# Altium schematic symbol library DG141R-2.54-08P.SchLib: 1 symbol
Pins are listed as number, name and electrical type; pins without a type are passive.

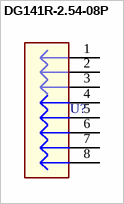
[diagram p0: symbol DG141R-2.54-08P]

## DG141R-2.54-08P
designator U?  (value not drawn)
DG129-5.0-03P-14-00AH
footprint DG141R-2.54-08P
pins: 1, 2, 3, 4, 5, 6, 7, 8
